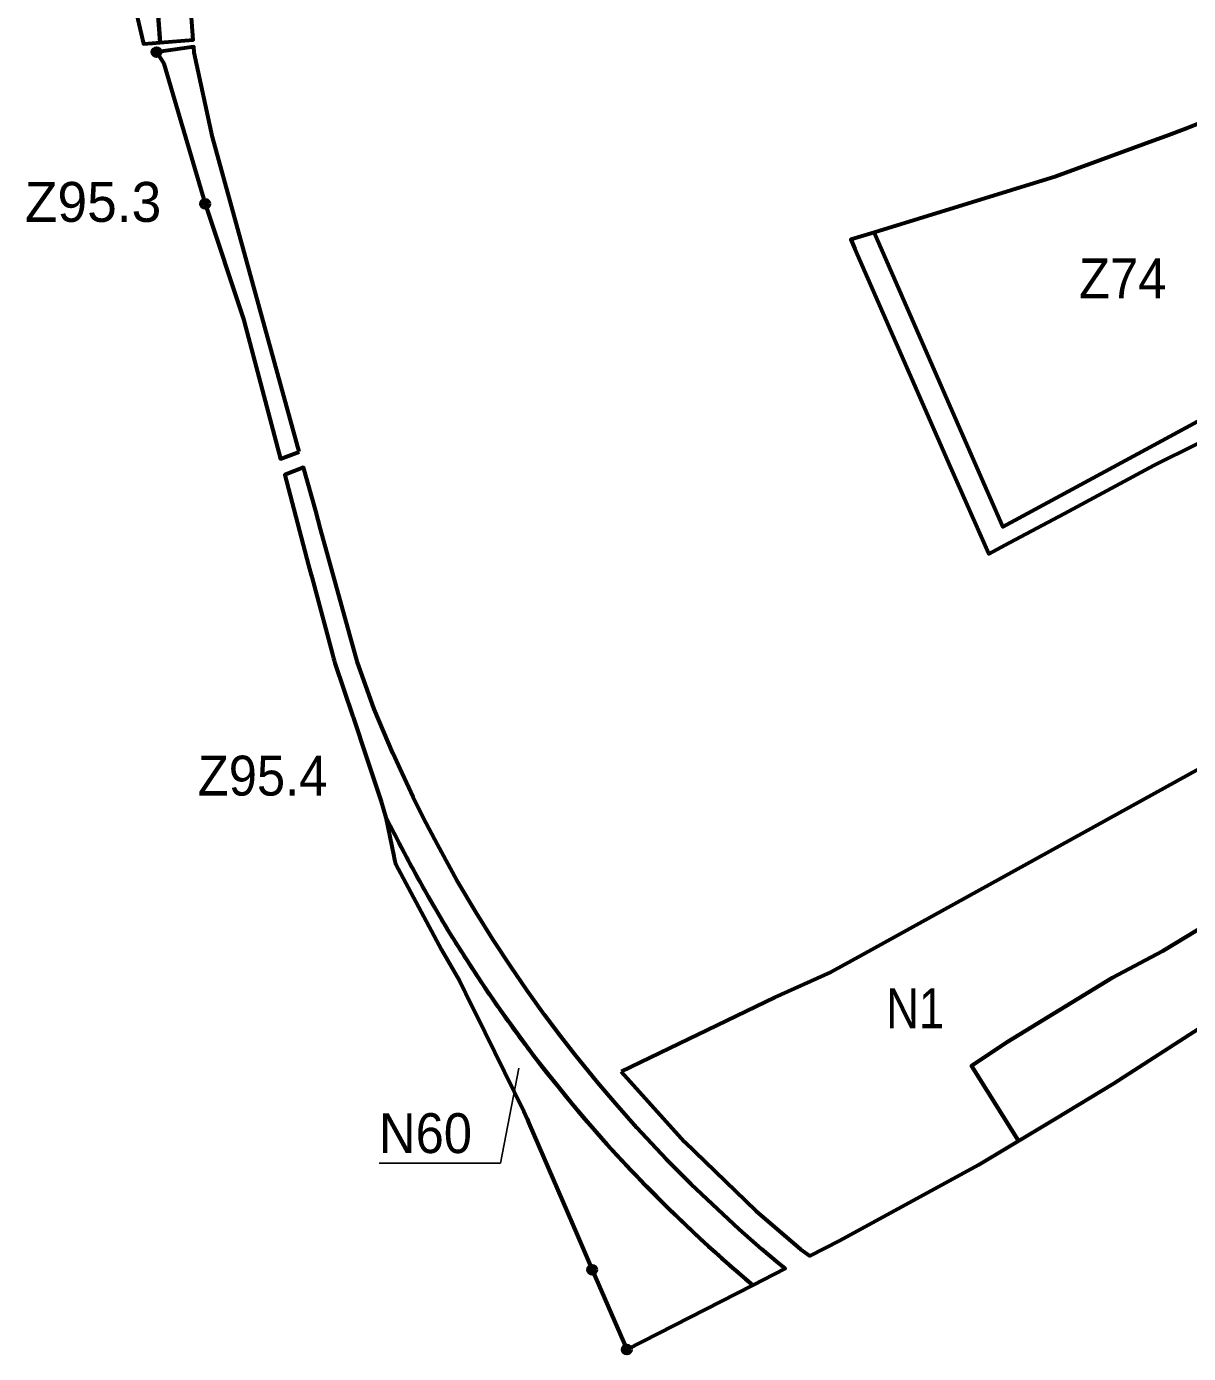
# Model space of a CAD drawing. Extents: x -650277 to -643425, y -1073980 to -1066720.
# Drawn here: x -649224 to -648525, y -1071170 to -1070373 of the extents above; entities that cross this region are included whole.
import ezdxf

# ---------------------------------------------------------------- set-up
doc = ezdxf.new("R2010")
doc.units = 0
doc.header["$LTSCALE"] = 9.6
doc.header["$PDMODE"] = 32
doc.header["$PDSIZE"] = 4.8
for name, color, linetype, lineweight in [('1', 7, 'Continuous', 60), ('15', 7, 'Continuous', 60), ('36', 7, 'Continuous', 60), ('42', 7, 'Continuous', 60), ('60', 7, 'Continuous', 60), ('63', 7, 'Continuous', 25), ('7', 7, 'Continuous', 60)]:
    doc.layers.add(name, color=color, linetype=linetype, lineweight=lineweight)

msp = doc.modelspace()

# ---------------------------------------------------------------- linework, layer by layer
at = {"layer": '1'}
msp.add_lwpolyline([(-648540.7, -1070928.6), (-648571.14, -1070944.67), (-648634.07, -1070983.17), (-648655.76, -1070997.5), (-648627.39, -1071042.65), (-648605.3, -1071029.34), (-648570.23, -1071008.2), (-648515.46, -1070972.94), (-648389.33, -1070889.79), (-648362.519, -1070872.788), (-648386.587, -1070833.807), (-648479.18, -1070891.26)], close=True, dxfattribs=at)
at = {"layer": '15'}
msp.add_lwpolyline([(-648440.531, -1070567.236), (-648550.72, -1070626.869), (-648636.757, -1070673.431), (-648655.178, -1070631.294), (-648714.161, -1070496.376), (-648728.255, -1070500.709), (-648725.835, -1070506.221), (-648668.207, -1070637.453), (-648645.331, -1070689.546), (-648632.652, -1070682.82), (-648599.66, -1070665.32), (-648545.76, -1070636.22), (-648494.04, -1070610.73)], dxfattribs=at)
at = {"layer": '36'}
msp.add_lwpolyline([(-648636.757, -1070673.431), (-648550.72, -1070626.869), (-648440.531, -1070567.236), (-648452.97, -1070544.21), (-648509.227, -1070426.957), (-648526.28, -1070433.85), (-648538.611, -1070438.388), (-648546.377, -1070441.246), (-648604.92, -1070462.79), (-648714.161, -1070496.376), (-648655.178, -1070631.294)], close=True, dxfattribs=at)
msp.add_lwpolyline([(-648636.757, -1070673.431), (-648550.72, -1070626.869), (-648440.531, -1070567.236), (-648452.97, -1070544.21), (-648509.227, -1070426.957), (-648526.28, -1070433.85), (-648538.611, -1070438.388), (-648546.377, -1070441.246), (-648604.92, -1070462.79), (-648714.161, -1070496.376), (-648655.178, -1070631.294)], close=True, dxfattribs=at)
at = {"layer": '42'}
for p, q in [((-648883.73, -1071120.13), (-648862.97, -1071168.09)), ((-648862.97, -1071168.09), (-648787.207, -1071129.363))]:
    msp.add_line(p, q, dxfattribs=at)
for points in [[(-649002.97, -1070857.609), (-649007.885, -1070848.153), (-649003.1, -1070871.35), (-649002.82, -1070872.69), (-649002.62, -1070873.69), (-649002.15, -1070875.96), (-648974.4, -1070927.77), (-648963.5, -1070946.45), (-648959.92, -1070953.73), (-648948.29, -1070977.37), (-648924.92, -1071024.89), (-648922.98, -1071029.49), (-648921.87, -1071032.04), (-648892.82, -1071099.15), (-648883.73, -1071120.13)], [(-648994.42, -1070874.053), (-648994.464, -1070873.974), (-648994.52, -1070873.867)], [(-648982.403, -1070895.812), (-648982.467, -1070895.704), (-648982.524, -1070895.601)], [(-648970.64, -1070915.778), (-648970.712, -1070915.663), (-648970.771, -1070915.564)], [(-648960.194, -1070932.542), (-648960.268, -1070932.429), (-648960.34, -1070932.313)], [(-648949.345, -1070949.096), (-648949.389, -1070949.031), (-648949.428, -1070948.972)], [(-648939.179, -1070963.89), (-648939.232, -1070963.818), (-648939.33, -1070963.675)], [(-648918.464, -1070992.141), (-648918.601, -1070991.969), (-648918.737, -1070991.784)]]:
    msp.add_lwpolyline(points, dxfattribs=at)
for start, end in [(206.85611, 208.07207), (208.08607, 209.71957), (209.73567, 211.25686), (211.27351, 212.56631), (212.58435, 213.8879), (213.89777, 215.07157), (215.08899, 217.38409), (217.41391, 230.04071)]:
    msp.add_arc((-648232.695, -1070467.567), 863.398, start, end, dxfattribs=at)
for p in [(-648883.73, -1071120.13), (-648862.97, -1071168.09)]:
    msp.add_point(p, dxfattribs=at)
at = {"layer": '60'}
for points in [[(-649145.424, -1070357.637), (-649143.633, -1070382.123), (-649123.693, -1070380.572), (-649125.503, -1070355.837)], [(-649059.951, -1070628.223), (-649112.14, -1070439.152), (-649123.138, -1070388.16), (-649123.385, -1070384.775), (-649145.73, -1070387.91)], [(-649145.73, -1070387.91), (-649141.48, -1070394.84), (-649132.07, -1070426.81), (-649116.56, -1070479.19)], [(-649116.56, -1070479.19), (-649093.2, -1070549.1), (-649071.33, -1070632.6), (-649059.951, -1070628.223)]]:
    msp.add_lwpolyline(points, dxfattribs=at)
msp.add_lwpolyline([(-648976.834, -1070864.527), (-648985.145, -1070848.538), (-648991.386, -1070835.954), (-648998.132, -1070821.723), (-649003.641, -1070809.566), (-649014.888, -1070782.994), (-649025.129, -1070754.377), (-649047.11, -1070674.743), (-649050.081, -1070663.981), (-649057.338, -1070637.689), (-649068.65, -1070642.23), (-649068.65, -1070642.23), (-649054.31, -1070696.44), (-649052.77, -1070702.25), (-649052.44, -1070703.48), (-649051.03, -1070708.74), (-649040.03, -1070750.06), (-649039.38, -1070752.51), (-649039.06, -1070753.72), (-649038.51, -1070755.38), (-649027.74, -1070787.51), (-649027.64, -1070787.8), (-649019.48, -1070812.18), (-649018.48, -1070815.18), (-649011.24, -1070836.79), (-649010.67, -1070838.5), (-649007.885, -1070848.153), (-648994.464, -1070873.974), (-648982.467, -1070895.704), (-648970.712, -1070915.663), (-648960.268, -1070932.429), (-648949.389, -1070949.031), (-648939.232, -1070963.818), (-648918.601, -1070991.969), (-648896.068, -1071020.184), (-648886.874, -1071031.044), (-648874.793, -1071044.773), (-648863.847, -1071056.723), (-648851.175, -1071069.886), (-648838.696, -1071082.562), (-648823.087, -1071097.562), (-648816.379, -1071103.782), (-648806.239, -1071112.938), (-648797, -1071121), (-648790.23, -1071126.818), (-648787.207, -1071129.363), (-648767.824, -1071119.455), (-648771.725, -1071116.233), (-648781.806, -1071107.721), (-648795.407, -1071095.8), (-648824.292, -1071068.677), (-648839.273, -1071053.556), (-648856.883, -1071034.761), (-648869.629, -1071020.411), (-648880.44, -1071007.703), (-648894.164, -1070990.806), (-648902.714, -1070979.812), (-648912.396, -1070966.893), (-648922.92, -1070952.242), (-648932.78, -1070937.887), (-648943.414, -1070921.659), (-648953.605, -1070905.299), (-648965.093, -1070885.794)], close=True, dxfattribs=at)
for p in [(-649145.73, -1070387.91), (-649116.56, -1070479.19)]:
    msp.add_point(p, dxfattribs=at)
at = {"layer": '63'}
msp.add_lwpolyline([(-649012, -1071056), (-648939, -1071056), (-648928, -1070999)], dxfattribs=at)
at = {"layer": '7'}
for points in [[(-649138.43, -1070283.6), (-649159.78, -1070279.52), (-649166.86, -1070273.48), (-649162.91, -1070317.47), (-649159.19, -1070358.82), (-649153.64, -1070382.9), (-649148.23, -1070382.48), (-649143.633, -1070382.123), (-649146.163, -1070347.543)], [(-648866.341, -1071000.881), (-648828.353, -1071043.265), (-648785.386, -1071084.634), (-648758.423, -1071107.756), (-648752.967, -1071111.861), (-648734.849, -1071102.599), (-648651.375, -1071057.109), (-648627.39, -1071042.65), (-648655.76, -1070997.5), (-648634.07, -1070983.17), (-648571.14, -1070944.67), (-648540.7, -1070928.6), (-648479.18, -1070891.26), (-648386.587, -1070833.807), (-648396.611, -1070817.573), (-648407.667, -1070799.667), (-648427.25, -1070767.95), (-648511.09, -1070814.7), (-648721.54, -1070930.88), (-648740.25, -1070941.21), (-648774.23, -1070956.42)]]:
    msp.add_lwpolyline(points, close=True, dxfattribs=at)

# ---------------------------------------------------------------- texts
at = {"layer": '63'}
msp.add_text('Z95.3', height=24, dxfattribs=at).set_placement((-649225, -1070490))
for s, width, p in [('Z74', 0.95, (-648591, -1070536)), ('Z95.4', 0.95, (-649121, -1070835)), ('N1', 0.85, (-648707, -1070975)), ('N60', 0.95, (-649012, -1071050))]:
    msp.add_text(s, height=24, dxfattribs=dict(at, width=width)).set_placement(p)

doc.saveas('drawing.dxf')
